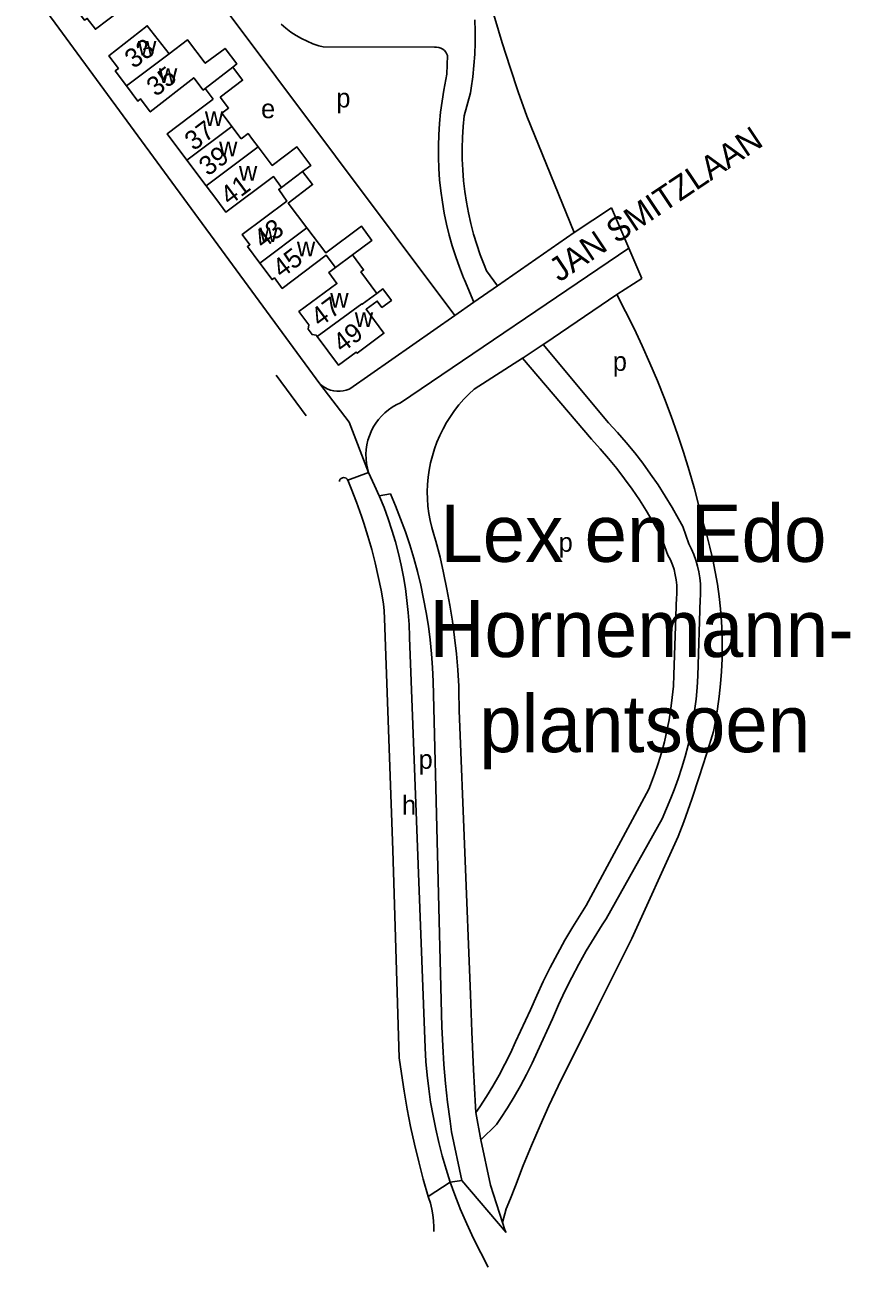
# Model space of a CAD drawing. Extents: x 160673 to 161924, y 382258 to 384145.
# Drawn here: x 161254.3 to 161427.9, y 382258.1 to 382519.2 of the extents above; entities that cross this region are included whole.
import ezdxf

# ---------------------------------------------------------------- set-up
doc = ezdxf.new("R2010")
doc.units = 0
for name, color, linetype in [('BLT_Basislijn', 7, 'Continuous'), ('BLT_Bebouwing', 7, 'Continuous'), ('BLT_Centroide', 7, 'Continuous'), ('BLT_Huisnummer', 7, 'Continuous'), ('BLT_Huisnummer_ tussenligend', 7, 'Continuous'), ('BLT_Onderverdeling_panden', 7, 'Continuous'), ('BLT_Sport_parknaam', 7, 'Continuous'), ('BLT_Straatnaam', 7, 'Continuous'), ('BLT_Vlakafsluiter', 7, 'Continuous')]:
    doc.layers.add(name, color=color, linetype=linetype)

msp = doc.modelspace()

# ---------------------------------------------------------------- linework, layer by layer
at = {"layer": 'BLT_Basislijn'}
for p, q in [((161278.95, 382546), (161344.75, 382458.1)), ((161316.36, 382443.76), (161254.33, 382528.3)), ((161317.03, 382514.54), (161340.44, 382514.47)), ((161346.68, 382500.07), (161348.03, 382504.91)), ((161359.89, 382500), (161369.86, 382475.58)), ((161369.86, 382475.58), (161377.69, 382480.74)), ((161353.7, 382464.33), (161369.86, 382475.58)), ((161333.3, 382439.79), (161381.3, 382472.25)), ((161351.38, 382467.52), (161353.7, 382464.33)), ((161346.78, 382465.57), (161348.74, 382460.88)), ((161348.74, 382460.88), (161353.7, 382464.33)), ((161384.02, 382465.86), (161378.79, 382462.53)), ((161344.75, 382458.1), (161348.74, 382460.88)), ((161322.65, 382442.71), (161344.75, 382458.1)), ((161377.06, 382435.53), (161363.33, 382452)), ((161348.79, 382442.63), (161358.96, 382449.14)), ((161373.44, 382432.09), (161358.96, 382449.14)), ((161307.18, 382445.54), (161313.51, 382437.03)), ((161328.82, 382420.24), (161331.21, 382420.61)), ((161392.65, 382413.76), (161393.93, 382410.14)), ((161388.22, 382411.44), (161389.55, 382407.72)), ((161391.35, 382398.97), (161390.81, 382382.59)), ((161395.81, 382382.38), (161396.32, 382398.47)), ((161329.98, 382394.41), (161331.7, 382345.77)), ((161335.21, 382390.42), (161338.47, 382304.23)), ((161340.2, 382381.2), (161342.01, 382308.64)), ((161345.61, 382379.3), (161345.66, 382375.11)), ((161345.66, 382375.11), (161348.03, 382315.45)), ((161372.38, 382334.11), (161385.51, 382358.57)), ((161391.69, 382348.59), (161381.97, 382327.2)), ((161333.05, 382302.14), (161331.7, 382345.77)), ((161357.52, 382305.45), (161360.65, 382312.23)), ((161362.1, 382303.45), (161365.25, 382310.29)), ((161349.14, 382290.6), (161350.21, 382284.87)), ((161353.48, 382288.09), (161350.21, 382284.87))]:
    msp.add_line(p, q, dxfattribs=at)
for points in [[(161359.89, 382500), (161358.08, 382505.11), (161356.35, 382510.24), (161354.69, 382515.4), (161353.12, 382520.58), (161351.61, 382525.78), (161350.19, 382531.01), (161348.84, 382536.25), (161348.13, 382539.17)], [(161308.21, 382519.31), (161309.22, 382518.46), (161310.27, 382517.68), (161311.36, 382516.96), (161312.5, 382516.32), (161313.68, 382515.74), (161314.88, 382515.23), (161316.12, 382514.8), (161317.03, 382514.54)], [(161348.95, 382520.23), (161349.02, 382517.84), (161349.02, 382515.44), (161348.93, 382513.05), (161348.76, 382510.66), (161348.52, 382508.28), (161348.19, 382505.9), (161348.03, 382504.91)], [(161340.44, 382514.47), (161340.9, 382514.48), (161341.35, 382514.41), (161341.78, 382514.27), (161342.18, 382514.05), (161342.54, 382513.77), (161342.84, 382513.42), (161343.08, 382513.03), (161343.19, 382512.77)], [(161343.19, 382512.77), (161343.06, 382508.84), (161342.43, 382505.49)], [(161342.43, 382505.49), (161342.04, 382503.16), (161341.73, 382500.82), (161341.5, 382498.46), (161341.35, 382496.1), (161341.28, 382493.74), (161341.29, 382491.37), (161341.37, 382489.01), (161341.54, 382486.65), (161341.79, 382484.29), (161342.11, 382481.95), (161342.52, 382479.62), (161343, 382477.3), (161343.57, 382475), (161344.21, 382472.73), (161344.92, 382470.47), (161345.71, 382468.24), (161346.58, 382466.04), (161346.78, 382465.57)], [(161346.68, 382500.07), (161346.46, 382497.8), (161346.33, 382495.52), (161346.27, 382493.24), (161346.3, 382490.97), (161346.4, 382488.69), (161346.58, 382486.42), (161346.85, 382484.15), (161347.19, 382481.9), (161347.61, 382479.66), (161348.11, 382477.43), (161348.69, 382475.23), (161349.34, 382473.04), (161350.07, 382470.88), (161350.88, 382468.75), (161351.38, 382467.52)], [(161363.33, 382452), (161363.68, 382452.23), (161378.79, 382462.53)], [(161378.79, 382462.53), (161380.64, 382458.97), (161382.42, 382455.38), (161384.12, 382451.76), (161385.76, 382448.1), (161387.32, 382444.41), (161388.8, 382440.69), (161390.21, 382436.94), (161391.55, 382433.16), (161392.81, 382429.36), (161393.99, 382425.53), (161395.1, 382421.68), (161396.13, 382417.81), (161396.95, 382414.48)], [(161358.96, 382449.14), (161359.08, 382449.21), (161363.33, 382452)], [(161316.36, 382443.76), (161316.86, 382443.32), (161317.42, 382442.95), (161318.01, 382442.65), (161318.63, 382442.41), (161319.28, 382442.26), (161319.94, 382442.18), (161320.6, 382442.18), (161321.26, 382442.26), (161321.91, 382442.42), (161322.53, 382442.66), (161322.65, 382442.71)], [(161348.79, 382442.63), (161347.68, 382441.59), (161346.62, 382440.5), (161345.61, 382439.35), (161344.67, 382438.15), (161343.8, 382436.9), (161342.99, 382435.61), (161342.25, 382434.27), (161341.58, 382432.9), (161340.98, 382431.5), (161340.46, 382430.07), (161340.01, 382428.61), (161339.64, 382427.13), (161339.35, 382425.63), (161339.13, 382424.12), (161339, 382422.6), (161338.95, 382421.08), (161338.97, 382419.55), (161339.08, 382418.03), (161339.27, 382416.52), (161339.53, 382415.02), (161339.87, 382413.53), (161340.3, 382412.06), (161340.77, 382410.67)], [(161333.3, 382439.79), (161332.42, 382439.36), (161331.58, 382438.87), (161330.77, 382438.3), (161330.02, 382437.67), (161329.32, 382436.98), (161328.68, 382436.24), (161328.1, 382435.45), (161327.59, 382434.61), (161327.14, 382433.74), (161326.77, 382432.83), (161326.48, 382431.89), (161326.26, 382430.93), (161326.12, 382429.96), (161326.06, 382428.98), (161326.08, 382428), (161326.18, 382427.03), (161326.36, 382426.06), (161326.6, 382425.11)], [(161377.06, 382435.53), (161378.95, 382433.49), (161380.78, 382431.39), (161382.55, 382429.24), (161384.25, 382427.05), (161385.89, 382424.8), (161387.46, 382422.51), (161388.97, 382420.17), (161390.41, 382417.79), (161391.79, 382415.37), (161392.65, 382413.76)], [(161373.44, 382432.09), (161375.28, 382430.1), (161377.05, 382428.05), (161378.77, 382425.96), (161380.42, 382423.81), (161382.01, 382421.62), (161383.54, 382419.38), (161384.99, 382417.1), (161386.38, 382414.77), (161387.7, 382412.41), (161388.22, 382411.44)], [(161326.6, 382425.11), (161327.88, 382422.37), (161328.82, 382420.24)], [(161322.25, 382423.52), (161322.1, 382423.74), (161321.88, 382423.92), (161321.63, 382424.02), (161321.36, 382424.05), (161321.09, 382423.99), (161320.85, 382423.87), (161320.65, 382423.68), (161320.52, 382423.43), (161320.47, 382423.21)], [(161325.09, 382415.94), (161324.07, 382418.85), (161322.97, 382421.74), (161322.25, 382423.52)], [(161328.82, 382420.24), (161328.9, 382420.07), (161329.85, 382417.73), (161330.72, 382415.37), (161331.52, 382412.98), (161332.24, 382410.56), (161332.89, 382408.12), (161333.45, 382405.67), (161333.94, 382403.19), (161334.35, 382400.71), (161334.68, 382398.21), (161334.94, 382395.7), (161335.11, 382393.19), (161335.2, 382390.67), (161335.21, 382390.42)], [(161340.2, 382381.2), (161340.06, 382384.11), (161339.84, 382387.03), (161339.55, 382389.93), (161339.17, 382392.83), (161338.71, 382395.71), (161338.18, 382398.58), (161337.56, 382401.44), (161336.87, 382404.28), (161336.1, 382407.09), (161335.26, 382409.89), (161334.34, 382412.66), (161333.34, 382415.4), (161332.27, 382418.12), (161331.21, 382420.61)], [(161329.71, 382397.54), (161329.22, 382400.41), (161328.65, 382403.26), (161328, 382406.1), (161327.27, 382408.91), (161326.47, 382411.71), (161325.59, 382414.48), (161325.09, 382415.94)], [(161396.95, 382414.48), (161397.7, 382411.96), (161398.38, 382409.42), (161398.98, 382406.85), (161399.5, 382404.27), (161399.94, 382401.68), (161400.3, 382399.07), (161400.59, 382396.45), (161400.79, 382393.83), (161400.92, 382391.2), (161400.96, 382388.57), (161400.92, 382385.94), (161400.81, 382383.31), (161400.61, 382380.68), (161400.34, 382378.06), (161399.98, 382375.46), (161399.55, 382372.86), (161399.12, 382370.67)], [(161340.77, 382410.67), (161341.62, 382407.34), (161342.39, 382404), (161343.08, 382400.63), (161343.7, 382397.25), (161344.23, 382393.86), (161344.68, 382390.46), (161345.06, 382387.04), (161345.36, 382383.62), (161345.57, 382380.2), (161345.61, 382379.3)], [(161393.93, 382410.14), (161394.51, 382409.02), (161395.01, 382407.86), (161395.44, 382406.67), (161395.79, 382405.46), (161396.07, 382404.22), (161396.27, 382402.97), (161396.39, 382401.72), (161396.42, 382400.45), (161396.38, 382399.19), (161396.32, 382398.47)], [(161389.55, 382407.72), (161390.05, 382406.75), (161390.47, 382405.74), (161390.82, 382404.7), (161391.09, 382403.64), (161391.28, 382402.56), (161391.39, 382401.47), (161391.42, 382400.38), (161391.38, 382399.29), (161391.35, 382398.97)], [(161329.71, 382397.54), (161329.88, 382396.02), (161329.98, 382394.41)], [(161390.81, 382382.59), (161390.68, 382380.22), (161390.46, 382377.86), (161390.16, 382375.51), (161389.78, 382373.17), (161389.33, 382370.84), (161388.79, 382368.53), (161388.18, 382366.24), (161387.49, 382363.97), (161386.73, 382361.72), (161385.89, 382359.51), (161385.51, 382358.57)], [(161395.81, 382382.38), (161395.67, 382379.93), (161395.45, 382377.49), (161395.14, 382375.05), (161394.76, 382372.63), (161394.3, 382370.22), (161393.77, 382367.82), (161393.15, 382365.45), (161392.46, 382363.09), (161391.69, 382360.76), (161390.85, 382358.46), (161390.12, 382356.65)], [(161399.12, 382370.67), (161397.67, 382365.9), (161396.14, 382361.16), (161394.54, 382356.44), (161392.86, 382351.74), (161391.69, 382348.59)], [(161376.55, 382331.35), (161388.34, 382352.37), (161390.12, 382356.65)], [(161360.65, 382312.23), (161361.95, 382315.22), (161363.33, 382318.18), (161364.78, 382321.1), (161366.3, 382323.99), (161367.89, 382326.84), (161369.55, 382329.65), (161371.27, 382332.41), (161372.38, 382334.11)], [(161365.25, 382310.29), (161366.53, 382313.22), (161367.89, 382316.12), (161369.31, 382318.99), (161370.81, 382321.82), (161372.37, 382324.61), (161374.01, 382327.36), (161375.71, 382330.07), (161376.55, 382331.35)], [(161381.97, 382327.2), (161374.67, 382312.65), (161366.46, 382296.18)], [(161348.03, 382315.45), (161348.29, 382307.56), (161348.63, 382299.67), (161349.05, 382291.79), (161349.14, 382290.6)], [(161342.01, 382308.64), (161342.2, 382304.66), (161342.46, 382300.69), (161342.81, 382296.73), (161343.23, 382292.77), (161343.74, 382288.82), (161344.06, 382286.57)], [(161357.52, 382305.45), (161356.44, 382303.08), (161355.28, 382300.75), (161354.06, 382298.45), (161352.76, 382296.19), (161351.4, 382293.98), (161349.97, 382291.8), (161349.14, 382290.6)], [(161339.15, 382272.97), (161338.11, 382276.61), (161337.15, 382280.27), (161336.26, 382283.95), (161335.45, 382287.65), (161334.72, 382291.36), (161334.06, 382295.09), (161333.49, 382298.84), (161333.05, 382302.14)], [(161338.47, 382304.23), (161338.64, 382301.36), (161338.9, 382298.49), (161339.24, 382295.62), (161339.65, 382292.77), (161340.15, 382289.93), (161340.72, 382287.11), (161341.37, 382284.3), (161342.1, 382281.52), (161342.9, 382278.75), (161343.78, 382276.01)], [(161362.1, 382303.45), (161360.99, 382301.01), (161359.8, 382298.6), (161358.55, 382296.24), (161357.22, 382293.91), (161355.83, 382291.62), (161354.36, 382289.38), (161353.48, 382288.09)], [(161366.46, 382296.18), (161364.51, 382292.06), (161362.65, 382287.9), (161360.85, 382283.71), (161359.13, 382279.48), (161357.48, 382275.23), (161356.47, 382272.52)], [(161344.06, 382286.57), (161346.24, 382276.34), (161343.78, 382276.01)], [(161350.21, 382284.87), (161352.24, 382275.38), (161354.73, 382267.54)], [(161343.78, 382276.01), (161344.74, 382273.29), (161345.77, 382270.6), (161345.87, 382270.35)], [(161340.33, 382265.61), (161340.34, 382266.57), (161340.28, 382267.83), (161340.13, 382269.09), (161339.91, 382270.33), (161339.61, 382271.55), (161339.23, 382272.76), (161339.15, 382272.97)], [(161356.47, 382272.52), (161355.56, 382270.35), (161354.73, 382267.54)], [(161345.87, 382270.35), (161347.25, 382267.24), (161348.69, 382264.16), (161350.21, 382261.11), (161351.77, 382258.13)], [(161354.73, 382267.54), (161355.22, 382266), (161355.5, 382265.43)]]:
    msp.add_lwpolyline(points, dxfattribs=at)
at = {"layer": 'BLT_Bebouwing'}
for p, q in [((161293.92, 382503.6), (161292.26, 382505.79)), ((161299.85, 382495.25), (161297.88, 382497.85))]:
    msp.add_line(p, q, dxfattribs=at)
for points in [[(161279.59, 382522.38), (161278.81, 382521.78), (161277, 382524.18), (161269.17, 382518.26), (161267.44, 382520.55), (161266.89, 382520.14), (161264.46, 382523.4)], [(161284.67, 382513.11), (161280.06, 382519), (161272.01, 382512.7), (161274, 382510.02), (161273.33, 382509.52), (161275.69, 382506.34)], [(161284.67, 382513.11), (161288.52, 382516.05), (161292.28, 382511.11), (161296.42, 382514.25), (161298.89, 382510.99), (161298.03, 382510.31)], [(161298.03, 382510.31), (161300.12, 382507.56), (161295.43, 382504.01)], [(161275.69, 382506.34), (161278.06, 382503.17), (161278.68, 382503.63), (161280.71, 382500.9), (161289.86, 382508.06), (161291.83, 382505.47), (161292.26, 382505.79)], [(161293.92, 382503.6), (161289.17, 382500), (161284.25, 382496.27), (161288.4, 382490.74)], [(161297.88, 382497.85), (161296.25, 382500), (161295.77, 382500.63), (161297.18, 382501.7), (161295.43, 382504.01)], [(161303.38, 382493.54), (161302.22, 382495.06), (161301.27, 382496.35), (161299.85, 382495.25)], [(161312.74, 382488.35), (161314.47, 382489.66), (161311.52, 382493.55), (161306.34, 382489.63), (161303.38, 382493.54)], [(161288.4, 382490.74), (161292.46, 382485.33)], [(161313.65, 382476.52), (161309.7, 382481.72), (161314.82, 382485.61), (161312.74, 382488.35)], [(161292.46, 382485.33), (161294.67, 382482.4), (161296.61, 382479.81), (161306.62, 382487.29), (161308.29, 382485.03)], [(161308.29, 382485.03), (161307.73, 382484.61), (161309.4, 382482.11), (161300.06, 382475.13), (161301.67, 382472.98), (161301.13, 382472.58), (161303.73, 382469.11)], [(161323.21, 382470.83), (161327.32, 382473.87), (161325.12, 382476.86), (161317.6, 382471.31), (161313.65, 382476.52)], [(161303.73, 382469.11), (161306.32, 382465.64), (161306.8, 382465.99), (161308.44, 382463.79), (161317.7, 382470.77), (161319.65, 382468.2)], [(161323.21, 382470.83), (161325.55, 382467.67), (161325.01, 382467.25), (161328.34, 382462.75)], [(161319.65, 382468.2), (161318.22, 382467.14), (161319.94, 382464.83), (161311.96, 382458.93), (161314.01, 382456.18), (161313.87, 382455.23), (161314.73, 382454.09), (161315.59, 382453.97), (161315.81, 382453.67)], [(161315.81, 382453.67), (161320.31, 382447.65), (161324, 382450.41), (161324.18, 382450.16), (161329.84, 382454.39), (161326.84, 382458.4), (161326.09, 382459.41), (161328.42, 382461.13), (161329.4, 382459.8), (161331.41, 382461.29), (161329.62, 382463.7), (161328.34, 382462.75)], [(161325.16, 382460.59), (161325.25, 382460.47), (161328.34, 382462.75)]]:
    msp.add_lwpolyline(points, dxfattribs=at)
at = {"layer": 'BLT_Onderverdeling_panden'}
for p, q in [((161275.69, 382506.34), (161284.67, 382513.11)), ((161292.26, 382505.79), (161298.03, 382510.31)), ((161288.4, 382490.74), (161297.88, 382497.85)), ((161292.46, 382485.33), (161303.38, 382493.54)), ((161308.29, 382485.03), (161312.74, 382488.35)), ((161303.73, 382469.11), (161313.65, 382476.52)), ((161319.65, 382468.2), (161323.21, 382470.83)), ((161325.16, 382460.59), (161315.81, 382453.67))]:
    msp.add_line(p, q, dxfattribs=at)
at = {"layer": 'BLT_Vlakafsluiter'}
for p, q in [((161322.25, 382423.52), (161326.6, 382425.11)), ((161339.15, 382272.97), (161343.78, 382276.01)), ((161346.24, 382276.34), (161355.5, 382265.43))]:
    msp.add_line(p, q, dxfattribs=at)
for points in [[(161377.69, 382480.74), (161381.3, 382472.25), (161384.02, 382465.86)], [(161316.36, 382443.76), (161322.49, 382435.67), (161326.6, 382425.11)]]:
    msp.add_lwpolyline(points, dxfattribs=at)

# ---------------------------------------------------------------- texts
at = {"layer": 'BLT_Centroide'}
for s, p in [('w', (161278.12, 382512.69)), ('w', (161282.52, 382506.97)), ('p', (161319.82, 382501.83)), ('w', (161292.19, 382497.92)), ('e', (161304, 382499.57)), ('w', (161295.17, 382491.59)), ('w', (161299.34, 382486.46)), ('w', (161303.64, 382473.52)), ('w', (161311.53, 382470.56)), ('w', (161318.54, 382459.75)), ('w', (161323.7, 382455.69)), ('p', (161377.95, 382446.47)), ('p', (161366.56, 382408.46)), ('p', (161337.12, 382362.85)), ('h', (161333.63, 382353.23))]:
    msp.add_text(s, height=4, dxfattribs=at).set_placement(p)
at = {"layer": 'BLT_Huisnummer'}
for s, rotation, p in [('33', 36.6457, (161277.22, 382509.86)), ('35', 38.0133, (161281.9, 382503.96)), ('37', 36.7657, (161289.84, 382492.59)), ('41', 36.7663, (161297.35, 382481.12)), ('43', 36.7663, (161304.38, 382471.97)), ('45', 37.0257, (161308.34, 382465.82)), ('47', 36.7825, (161316.37, 382455.56)), ('49', 36.7722, (161321.04, 382450.14))]:
    msp.add_text(s, height=4, rotation=rotation, dxfattribs=at).set_placement(p)
at = {"layer": 'BLT_Huisnummer_ tussenligend'}
msp.add_text('39', height=4, rotation=36.7628, dxfattribs=at).set_placement((161292.84, 382487.27))
at = {"layer": 'BLT_Sport_parknaam'}
for s, p in [('Lex en Edo', (161341.68, 382406.34)), ('Hornemann-', (161339.38, 382386.34)), ('plantsoen', (161349.86, 382366.34))]:
    msp.add_text(s, height=12, dxfattribs=at).set_placement(p)
at = {"layer": 'BLT_Straatnaam'}
msp.add_text('JAN SMITZLAAN', height=5, rotation=33.8259, dxfattribs=at).set_placement((161366.71, 382465.01))

doc.saveas('drawing.dxf')
